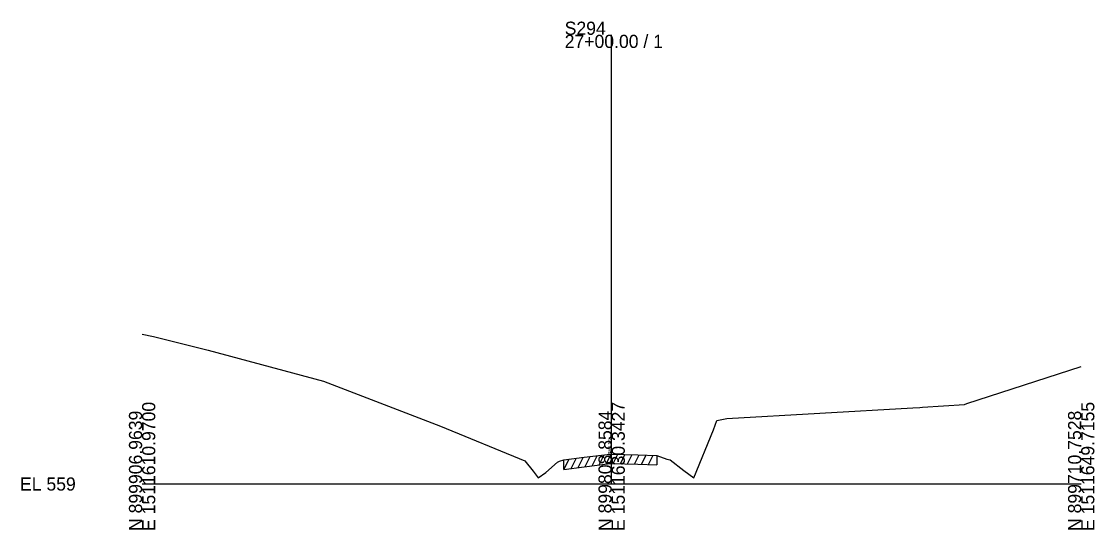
# Model space of a CAD drawing. Extents: x 974 to 2203, y -10 to 19041.
# Drawn here: x 1974.3 to 2202.8, y 13990.3 to 14098.5 of the extents above; entities that cross this region are included whole.
import ezdxf

# ---------------------------------------------------------------- set-up
doc = ezdxf.new("R2010")
doc.units = 0
for name, color, linetype in [('RD_GPK_XS_Cell', 7, 'Continuous'), ('RD_XS_ExGround', 7, 'Continuous'), ('RD_XS_ExPaveRet', 7, 'Continuous'), ('RD_XS_TX_Elev_EX', 7, 'Continuous')]:
    doc.layers.add(name, color=color, linetype=linetype)

msp = doc.modelspace()

# ---------------------------------------------------------------- linework, layer by layer
at = {"layer": 'RD_GPK_XS_Cell'}
for p, q in [((2100, 14000), (2100, 14095.62)), ((2000, 14000), (2100, 14000)), ((2100, 14000), (2200, 14000))]:
    msp.add_line(p, q, dxfattribs=at)
at = {"layer": 'RD_XS_ExGround'}
msp.add_lwpolyline([(2000, 14031.87), (2002.41, 14031.37), (2014.1, 14028.48), (2038.66, 14021.89), (2063.56, 14012.3), (2081.54, 14004.91), (2083.31, 14002.7), (2084.38, 14001.29), (2085.96, 14002.43), (2088.44, 14004.68), (2088.89, 14004.86), (2089.85, 14005.12), (2094.12, 14005.68), (2099.69, 14006.37), (2100, 14006.36), (2105.57, 14006.23), (2109.64, 14006.08), (2111.73, 14005.3), (2112.46, 14005.11), (2115.35, 14002.9), (2117.47, 14001.32), (2121.67, 14011.52), (2122.42, 14013.55), (2124.53, 14013.92), (2164.16, 14016.23), (2165.6, 14016.31), (2166.2, 14016.32), (2175.17, 14016.93), (2175.63, 14017.13), (2200, 14025.01)], dxfattribs=at)
at = {"layer": 'RD_XS_ExPaveRet'}
for p, q in [((2089.85, 14003.12), (2090.92, 14005.26)), ((2089.85, 14003.12), (2089.85, 14005.12)), ((2091.35, 14003.32), (2092.42, 14005.46)), ((2092.85, 14003.52), (2093.92, 14005.66)), ((2094.35, 14003.71), (2095.42, 14005.84)), ((2095.85, 14003.9), (2096.92, 14006.03)), ((2097.35, 14004.08), (2098.42, 14006.21)), ((2098.85, 14004.27), (2099.9, 14006.37)), ((2100.35, 14004.35), (2101.34, 14006.33)), ((2101.85, 14004.32), (2102.84, 14006.29)), ((2103.35, 14004.28), (2104.34, 14006.26)), ((2104.85, 14004.25), (2105.84, 14006.22)), ((2106.35, 14004.2), (2107.34, 14006.17)), ((2107.85, 14004.15), (2108.84, 14006.11)), ((2109.64, 14006.08), (2109.64, 14004.08)), ((2089.85, 14003.12), (2094.12, 14003.68)), ((2094.12, 14003.68), (2099.69, 14004.37)), ((2099.69, 14004.37), (2100, 14004.36)), ((2100, 14004.36), (2105.57, 14004.23)), ((2105.57, 14004.23), (2109.64, 14004.08))]:
    msp.add_line(p, q, dxfattribs=at)

# ---------------------------------------------------------------- texts
at = {"layer": 'RD_GPK_XS_Cell'}
for s, p in [('S294', (2090, 14095.62)), ('27+00.00 / 1', (2090, 14092.82)), ('EL 559', (1974, 13998.6))]:
    msp.add_text(s, height=2.8, dxfattribs=at).set_placement(p)
for s, p in [('E 1511610.9700', (2002.8, 13990)), ('E 1511630.3427', (2102.8, 13990)), ('E 1511649.7155', (2202.8, 13990)), ('N 899906.9639', (2000, 13990)), ('N 899808.8584', (2100, 13990)), ('N 899710.7528', (2200, 13990))]:
    msp.add_text(s, height=2.8, rotation=90, dxfattribs=at).set_placement(p)
at = {"layer": 'RD_XS_TX_Elev_EX'}
msp.add_text('562.18', height=0.75, rotation=90, dxfattribs=at).set_placement((2100, 14006.36))

doc.saveas('drawing.dxf')
